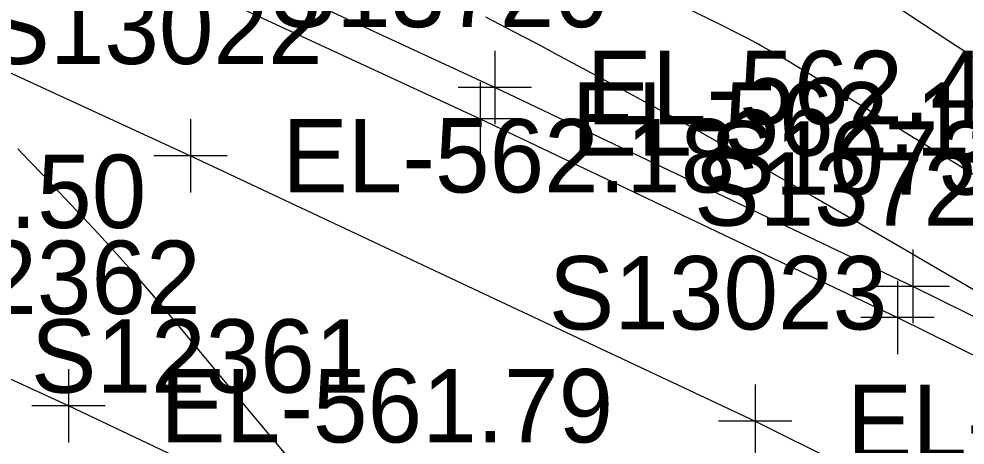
# Model space of a CAD drawing. Extents: x 1729869 to 1735532, y 648588 to 653771.
# Drawn here: x 1730520.1 to 1730571.7, y 652510 to 652533.3 of the extents above; entities that cross this region are included whole.
import ezdxf

# ---------------------------------------------------------------- set-up
doc = ezdxf.new("R2010")
doc.units = 0
for name, color, linetype in [('SURVEY - CONTOURS - Index with Text', 7, 'Continuous'), ('SURVEY - CONTOURS - Intermediate with optional Text', 7, 'Continuous'), ('SURVEY - DTM - Breaklines', 7, 'Continuous'), ('SURVEY - DTM - Breaklines - Points - Elevations', 7, 'Continuous'), ('SURVEY - DTM - Breaklines - Points - Locators', 7, 'Continuous'), ('SURVEY - DTM - Breaklines - Points - Numbers', 7, 'Continuous'), ('SURVEY - TRANSPORTATION - Features', 7, 'Continuous'), ('SURVEY - TRANSPORTATION - Features - Points - Elevations', 7, 'Continuous'), ('SURVEY - TRANSPORTATION - Features - Points - Locators', 7, 'Continuous'), ('SURVEY - TRANSPORTATION - Features - Points - Numbers', 7, 'Continuous'), ('SURVEY - TRANSPORTATION - Roads', 7, 'Continuous'), ('SURVEY - TRANSPORTATION - Roads - Points - Elevations', 7, 'Continuous'), ('SURVEY - TRANSPORTATION - Roads - Points - Locators', 7, 'Continuous'), ('SURVEY - TRANSPORTATION - Roads - Points - Numbers', 7, 'Continuous')]:
    doc.layers.add(name, color=color, linetype=linetype)

msp = doc.modelspace()

# ---------------------------------------------------------------- linework, layer by layer
at = {"layer": 'SURVEY - CONTOURS - Index with Text'}
msp.add_lwpolyline([(1730574.778, 652529.523), (1730571.295, 652531.755), (1730570.12, 652532.515), (1730568.047, 652533.867), (1730566.767, 652534.704)], dxfattribs=at)
at = {"layer": 'SURVEY - CONTOURS - Intermediate with optional Text'}
for points in [[(1730572.512, 652524.571), (1730570.651, 652525.712), (1730568.389, 652527.089), (1730564.514, 652529.47), (1730563.115, 652530.327), (1730562.436, 652530.737), (1730562.097, 652530.939), (1730561.743, 652531.147), (1730561.389, 652531.351), (1730561.035, 652531.552), (1730560.682, 652531.749), (1730560.328, 652531.943), (1730559.78, 652532.236), (1730559.24, 652532.515), (1730558.542, 652532.865), (1730554.917, 652534.65)], [(1730574.005, 652517.41), (1730571.235, 652519.046), (1730569.422, 652520.109), (1730568.275, 652520.776), (1730563.495, 652523.535), (1730560.146, 652525.469), (1730559.115, 652526.058), (1730558.088, 652526.64), (1730557.079, 652527.202), (1730556.006, 652527.79), (1730553.61, 652529.092), (1730549.351, 652531.393), (1730548.41, 652531.895), (1730547.606, 652532.316), (1730546.732, 652532.767), (1730545.576, 652533.356)], [(1730535.531, 652508.509), (1730532.197, 652512.519), (1730528.559, 652516.891), (1730527.98, 652517.582), (1730527.384, 652518.285), (1730526.803, 652518.962), (1730526.316, 652519.518), (1730525.787, 652520.111), (1730525.197, 652520.76), (1730524.467, 652521.55), (1730523.635, 652522.441), (1730522.615, 652523.526), (1730521.451, 652524.754), (1730520.74, 652525.498), (1730520.076, 652526.186)]]:
    msp.add_lwpolyline(points, dxfattribs=at)
at = {"layer": 'SURVEY - DTM - Breaklines'}
msp.add_lwpolyline([(1730701.831, 652448.311), (1730680.069, 652460.611), (1730658.147, 652472.777), (1730635.92, 652484.613), (1730613.644, 652496.246), (1730591.357, 652507.57), (1730568.855, 652518.695), (1730546.07, 652529.531), (1730523.318, 652540.081), (1730500.602, 652550.622), (1730482.95, 652558.576)], dxfattribs=at)
at = {"layer": 'SURVEY - DTM - Breaklines - Points - Locators'}
for p, q in [((1730546.07, 652531.531), (1730546.07, 652527.531)), ((1730548.07, 652529.531), (1730544.07, 652529.531)), ((1730568.855, 652520.695), (1730568.855, 652516.695)), ((1730570.855, 652518.695), (1730566.855, 652518.695))]:
    msp.add_line(p, q, dxfattribs=at)
at = {"layer": 'SURVEY - TRANSPORTATION - Features'}
msp.add_lwpolyline([(1730482.128, 652556.778), (1730499.818, 652548.902), (1730522.526, 652538.364), (1730545.264, 652527.819), (1730568.012, 652517.002), (1730590.497, 652505.885), (1730612.785, 652494.561), (1730635.04, 652482.939), (1730657.237, 652471.119), (1730679.148, 652458.959), (1730700.909, 652446.658)], dxfattribs=at)
at = {"layer": 'SURVEY - TRANSPORTATION - Features - Points - Locators'}
for p, q in [((1730545.264, 652529.819), (1730545.264, 652525.819)), ((1730547.264, 652527.819), (1730543.264, 652527.819)), ((1730568.012, 652519.002), (1730568.012, 652515.002)), ((1730570.012, 652517.002), (1730566.012, 652517.002))]:
    msp.add_line(p, q, dxfattribs=at)
at = {"layer": 'SURVEY - TRANSPORTATION - Roads'}
for points in [[(1730477.741, 652549.555), (1730480.41, 652548.336), (1730500.427, 652539.207), (1730529.488, 652525.811), (1730560.256, 652511.345), (1730583.532, 652499.762), (1730613.819, 652484.316), (1730649.217, 652465.696), (1730673.763, 652452.23)], [(1730639.01, 652453.881), (1730623.049, 652462.2), (1730610.635, 652468.672), (1730596.418, 652476.006), (1730574.978, 652486.792), (1730557.081, 652495.716), (1730531.873, 652507.902), (1730522.838, 652512.189), (1730497.394, 652523.874), (1730478.726, 652532.248)]]:
    msp.add_lwpolyline(points, dxfattribs=at)
at = {"layer": 'SURVEY - TRANSPORTATION - Roads - Points - Locators'}
for p, q in [((1730529.488, 652527.811), (1730529.488, 652523.811)), ((1730531.488, 652525.811), (1730527.488, 652525.811)), ((1730522.838, 652514.189), (1730522.838, 652510.189)), ((1730560.256, 652513.345), (1730560.256, 652509.345)), ((1730524.838, 652512.189), (1730520.838, 652512.189)), ((1730562.256, 652511.345), (1730558.256, 652511.345))]:
    msp.add_line(p, q, dxfattribs=at)

# ---------------------------------------------------------------- texts
at = {"layer": 'SURVEY - DTM - Breaklines - Points - Elevations'}
msp.add_text('EL-562.40', height=4, dxfattribs=at).set_placement((1730551.07, 652527.531))
at = {"layer": 'SURVEY - DTM - Breaklines - Points - Numbers'}
msp.add_text('S10731', height=4, dxfattribs=at).set_placement((1730557.773, 652523.695))
at = {"layer": 'SURVEY - TRANSPORTATION - Features - Points - Elevations'}
msp.add_text('EL-562.14', height=4, dxfattribs=at).set_placement((1730550.264, 652525.819))
at = {"layer": 'SURVEY - TRANSPORTATION - Features - Points - Numbers'}
for s, p in [('S13720', (1730533.851, 652532.819)), ('S13721', (1730556.93, 652522.002))]:
    msp.add_text(s, height=4, dxfattribs=at).set_placement(p)
at = {"layer": 'SURVEY - TRANSPORTATION - Roads - Points - Elevations'}
for s, p in [('EL-562.18', (1730534.488, 652523.811)), ('EL-561.50', (1730502.394, 652521.874)), ('EL-561.79', (1730527.838, 652510.189)), ('EL-562.60', (1730565.256, 652509.345))]:
    msp.add_text(s, height=4, dxfattribs=at).set_placement(p)
at = {"layer": 'SURVEY - TRANSPORTATION - Roads - Points - Numbers'}
for s, p in [('S13022', (1730518.248, 652530.811)), ('S12362', (1730511.598, 652517.189)), ('S13023', (1730549.016, 652516.345)), ('S12361', (1730520.791, 652512.902))]:
    msp.add_text(s, height=4, dxfattribs=at).set_placement(p)

doc.saveas('drawing.dxf')
